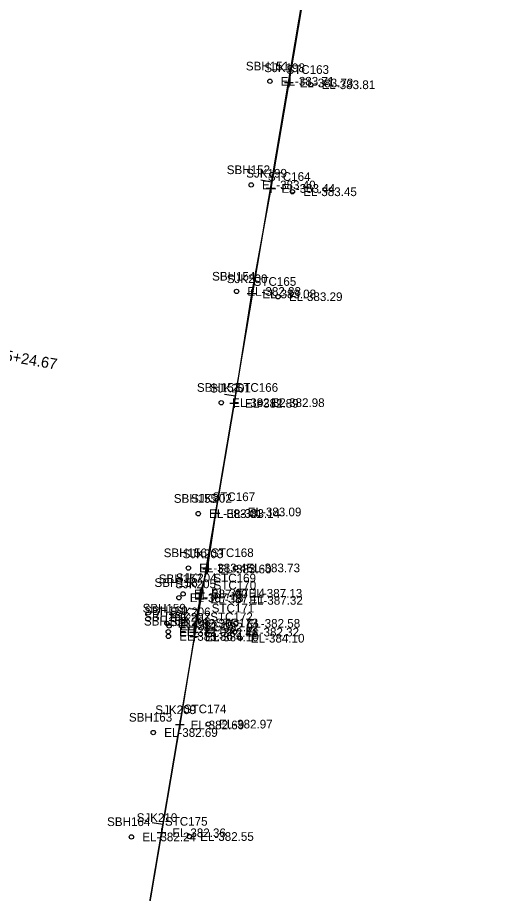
# Model space of a CAD drawing. Extents: x 1189978 to 1314812, y 571533 to 629339.
# Drawn here: x 1217888.2 to 1218104.7, y 621960.6 to 622363.9 of the extents above; entities that cross this region are included whole.
import ezdxf

# ---------------------------------------------------------------- set-up
doc = ezdxf.new("R2010")
doc.units = 0
for name, color, linetype in [('SURVEY - CENTERLINE - Preliminary Curve Text', 7, 'Continuous'), ('SURVEY - DRAINAGE - Bridge Hydraulic Data - Points - Elevations', 7, 'Continuous'), ('SURVEY - DRAINAGE - Bridge Hydraulic Data - Points - Numbers', 7, 'Continuous'), ('SURVEY - DRAINAGE - Bridge Hydraulic Data with Text', 7, 'Continuous'), ('SURVEY - DTM - Breaklines', 7, 'Continuous'), ('SURVEY - DTM - Spot Points - Elevations', 7, 'Continuous'), ('SURVEY - DTM - Spot Points - Locators', 7, 'Continuous'), ('SURVEY - DTM - Spot Points - Point Numbers', 7, 'Continuous')]:
    doc.layers.add(name, color=color, linetype=linetype)

msp = doc.modelspace()

# ---------------------------------------------------------------- linework, layer by layer
at = {"layer": 'SURVEY - DRAINAGE - Bridge Hydraulic Data with Text'}
for p, q in [((1217654.48, 620217.59), (1218104.66, 622874.85)), ((1217654.48, 620217.59), (1218104.66, 622874.85)), ((1217654.48, 620217.59), (1218104.66, 622874.85)), ((1218005.26, 622288.09), (1218000.33, 622288.92)), ((1217988.55, 622189.49), (1217983.62, 622190.33)), ((1217971.85, 622090.89), (1217966.92, 622091.73)), ((1217955.15, 621992.3), (1217950.22, 621993.13))]:
    msp.add_line(p, q, dxfattribs=at)
at = {"layer": 'SURVEY - DTM - Breaklines'}
for p, q in [((1218015.16, 622333.72), (1218011.16, 622333.72)), ((1218013.16, 622335.72), (1218013.16, 622331.72)), ((1218006.81, 622285.15), (1218002.81, 622285.15)), ((1218004.81, 622287.15), (1218004.81, 622283.15)), ((1217998.02, 622236.59), (1217994.02, 622236.59)), ((1217996.02, 622238.59), (1217996.02, 622234.59)), ((1217988, 622188.23), (1217988, 622184.23)), ((1217990, 622186.23), (1217986, 622186.23)), ((1217979.41, 622137.51), (1217979.41, 622133.51)), ((1217981.41, 622135.51), (1217977.41, 622135.51)), ((1217975.51, 622111.95), (1217975.51, 622107.95)), ((1217977.51, 622109.95), (1217973.51, 622109.95)), ((1217972.39, 622100.9), (1217972.39, 622096.9)), ((1217974.11, 622096.12), (1217970.11, 622096.12)), ((1217974.39, 622098.9), (1217970.39, 622098.9)), ((1217972.11, 622098.12), (1217972.11, 622094.12)), ((1217971.75, 622083.22), (1217967.75, 622083.22)), ((1217969.75, 622085.22), (1217969.75, 622081.22)), ((1217971.41, 622080.7), (1217967.41, 622080.7)), ((1217969.41, 622082.7), (1217969.41, 622078.7)), ((1217969.61, 622080.68), (1217969.61, 622076.68)), ((1217971.61, 622078.68), (1217967.61, 622078.68)), ((1217962.92, 622040.16), (1217962.92, 622036.16)), ((1217964.92, 622038.16), (1217960.92, 622038.16)), ((1217954.49, 621990.51), (1217954.49, 621986.51)), ((1217956.49, 621988.51), (1217952.49, 621988.51))]:
    msp.add_line(p, q, dxfattribs=at)
msp.add_lwpolyline([(1218021.58, 622384.02), (1218013.16, 622333.72), (1218004.81, 622285.15), (1217996.02, 622236.59), (1217988, 622186.23), (1217979.41, 622135.51), (1217975.51, 622109.95), (1217972.39, 622098.9), (1217972.11, 622096.12), (1217969.75, 622083.22), (1217969.41, 622080.7), (1217969.61, 622078.68), (1217962.92, 622038.16), (1217954.49, 621988.51), (1217946.09, 621938.59), (1217937.89, 621890.02), (1217934.79, 621871.87), (1217933.25, 621869.16), (1217932.85, 621864.71), (1217933.01, 621862.02), (1217929.4, 621840.5), (1217920.86, 621789.37), (1217912.92, 621742.33), (1217904.38, 621692.99)], dxfattribs=at)
at = {"layer": 'SURVEY - DTM - Spot Points - Locators'}
for centre in [(1218004.46, 622334.5), (1218023.28, 622332.9), (1217995.83, 622286.76), (1218014.8, 622283.64), (1217989.08, 622237.74), (1218008.2, 622235.33), (1217982.06, 622186.53), (1217999.97, 622186.54), (1217971.43, 622135.44), (1217989.27, 622136.23), (1217966.89, 622110.42), (1217988.65, 622110.46), (1217964.5, 622098.47), (1217989.68, 622098.78), (1217962.58, 622096.71), (1217989.93, 622095.52), (1217957.06, 622084.92), (1217958.05, 622083.76), (1217988.72, 622084.94), (1217957.64, 622081.1), (1217957.69, 622078.92), (1217988.21, 622080.92), (1217990.69, 622078.1), (1217976.04, 622038.55), (1217950.76, 622034.69), (1217940.7, 621986.62), (1217967.35, 621986.8)]:
    msp.add_circle(centre, 1, dxfattribs=at)

# ---------------------------------------------------------------- texts
at = {"layer": 'SURVEY - CENTERLINE - Preliminary Curve Text'}
msp.add_text('PT 65+24.67', height=5, rotation=350.1256, dxfattribs=at).set_placement((1217868.1, 622208.33))
at = {"layer": 'SURVEY - DRAINAGE - Bridge Hydraulic Data - Points - Elevations'}
for s, p in [('EL-383.73', (1218018.16, 622331.72)), ('EL-383.44', (1218009.81, 622283.15)), ('EL-383.08', (1218001.02, 622234.59)), ('EL-382.89', (1217993, 622184.23)), ('EL-383.14', (1217984.41, 622133.51)), ('EL-383.60', (1217980.51, 622107.95)), ('EL-387.14', (1217977.39, 622096.9)), ('EL-387.11', (1217977.11, 622094.12)), ('EL-382.02', (1217974.75, 622081.22)), ('EL-382.46', (1217974.41, 622078.7)), ('EL-384.10', (1217974.61, 622076.68)), ('EL-382.69', (1217967.92, 622036.16)), ('EL-382.36', (1217959.49, 621986.51))]:
    msp.add_text(s, height=4, dxfattribs=at).set_placement(p)
at = {"layer": 'SURVEY - DRAINAGE - Bridge Hydraulic Data - Points - Numbers'}
for s, p in [('SJK198', (1218001.87, 622338.72)), ('SJK199', (1217993.56, 622290.15)), ('SJK200', (1217984.6, 622241.59)), ('SJK201', (1217976.92, 622191.23)), ('SJK202', (1217968.17, 622140.51)), ('SJK203', (1217964.27, 622114.95)), ('SJK204', (1217961.15, 622103.9)), ('SJK205', (1217960.87, 622101.12)), ('SJK206', (1217958.4, 622088.22)), ('SJK207', (1217958.17, 622085.7)), ('SJK208', (1217958.33, 622083.68)), ('SJK209', (1217951.67, 622043.16)), ('SJK210', (1217943.08, 621993.51))]:
    msp.add_text(s, height=4, dxfattribs=at).set_placement(p)
at = {"layer": 'SURVEY - DTM - Spot Points - Elevations'}
for s, p in [('EL-383.71', (1218009.46, 622332.5)), ('EL-383.81', (1218028.28, 622330.9)), ('EL-383.40', (1218000.83, 622284.76)), ('EL-383.45', (1218019.8, 622281.64)), ('EL-382.88', (1217994.08, 622235.74)), ('EL-383.29', (1218013.2, 622233.33)), ('EL-382.82', (1217987.06, 622184.53)), ('EL-382.98', (1218004.97, 622184.54)), ('EL-383.01', (1217976.43, 622133.44)), ('EL-383.09', (1217994.27, 622134.23)), ('EL-383.46', (1217971.89, 622108.42)), ('EL-383.73', (1217993.65, 622108.46)), ('EL-387.00', (1217969.5, 622096.47)), ('EL-387.13', (1217994.68, 622096.78)), ('EL-387.13', (1217967.58, 622094.71)), ('EL-387.32', (1217994.93, 622093.52)), ('EL-382.30', (1217962.06, 622082.92)), ('EL-382.15', (1217963.05, 622081.76)), ('EL-382.58', (1217993.72, 622082.94)), ('EL-382.02', (1217962.64, 622079.1)), ('EL-383.86', (1217962.69, 622076.92)), ('EL-382.32', (1217993.21, 622078.92)), ('EL-384.10', (1217995.69, 622076.1)), ('EL-382.97', (1217981.04, 622036.55)), ('EL-382.69', (1217955.76, 622032.69)), ('EL-382.24', (1217945.7, 621984.62)), ('EL-382.55', (1217972.35, 621984.8))]:
    msp.add_text(s, height=4, dxfattribs=at).set_placement(p)
at = {"layer": 'SURVEY - DTM - Spot Points - Point Numbers'}
for s, p in [('SBH151', (1217993.38, 622339.5)), ('STC163', (1218012.05, 622337.9)), ('SBH152', (1217984.59, 622291.76)), ('STC164', (1218003.56, 622288.64)), ('SBH154', (1217977.84, 622242.74)), ('STC165', (1217996.96, 622240.33)), ('SBH153', (1217970.83, 622191.53)), ('STC166', (1217988.62, 622191.54)), ('SBH155', (1217960.19, 622140.44)), ('STC167', (1217978.03, 622141.23)), ('SBH156', (1217955.54, 622115.42)), ('STC168', (1217977.36, 622115.46)), ('SBH157', (1217953.26, 622103.47)), ('STC169', (1217978.42, 622103.78)), ('SBH158', (1217951.29, 622101.71)), ('STC170', (1217978.51, 622100.52)), ('SBH159', (1217945.81, 622089.92)), ('SBH160', (1217946.64, 622088.76)), ('STC171', (1217977.64, 622089.94)), ('SBH162', (1217946.45, 622083.92)), ('SBH161', (1217946.56, 622086.1)), ('STC172', (1217976.97, 622085.92)), ('STC173', (1217979.45, 622083.1)), ('STC174', (1217964.8, 622043.55)), ('SBH163', (1217939.52, 622039.69)), ('SBH164', (1217929.46, 621991.62)), ('STC175', (1217956.11, 621991.8))]:
    msp.add_text(s, height=4, dxfattribs=at).set_placement(p)

doc.saveas('drawing.dxf')
